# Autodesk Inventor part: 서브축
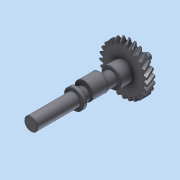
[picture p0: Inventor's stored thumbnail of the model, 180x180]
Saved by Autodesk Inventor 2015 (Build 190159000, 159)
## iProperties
Created: 2018-07
Part Number: 서브축
Material: 강철
Document SubType Name: Modeling
Designer: mduedu
Categories: <?xml version="1.0" encoding="UTF-16"?> <MemberInstance><Categories><FamilyTemplate><FamilyTemplateParameter ValueType="xs:double" Id="1" ObjectReferenceKey="da
Density: 7.85 g/cm^3
Mass: 513.764 g
Surface Area: 178.04 cm^2
Volume: 65.4477 cm^3
Appearance: 강철
Author: mduedu
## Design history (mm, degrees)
sketch "Sketch1"
  geometry: C1 r 30.864 at (0, 0)
  constraints: 1 centre point
  dimensions: "d0" = 61.72879 diameter of C1 (= da_da)
extrude "Extrusion1" new body sketch "Sketch1" distance "d1" = 10 (= da_b); taper "d2" = 0 deg
workplane "Work Plane2"
sketch "Sketch2"
  geometry: C1 r 30.864 at (0, 0) reference; C2 r 29.013 at (0, 0)
  constraints: 1 centre point, 1 coincident
  dimensions: "d3" = 58.02632 diameter of C2 (= da_dw)
feature "피치 지름" sketch "Sketch2" dims "d4" = 10, "d5" = 0
workplane "Work Plane8"
workplane "Work Plane9"
feature "스퍼 기어" dims "da_b" = 10, "da_d" = 57.73503, "da_aw" = 44.1, "da_da" = 61.72879, "da_df" = 52.73503, "da_dw" = 58.02632, angle "da_beta" = 30 deg, "da_lefttooth" = 10, "da_righttooth" = 0
sketch "스케치3"
  geometry: C1 r 12.5 at (0, 0); 1 further point
  constraints: 1 centre point, 1 coincident
  dimensions: "d49" = 25 diameter of C1
extrude "돌출2" join sketch "스케치3" distance "d50" = 16; taper "d51" = 0 deg
sketch "스케치4"
  geometry: C1 r 8.5 at (0, 0); 1 further point
  constraints: 1 centre point, 1 coincident
  dimensions: "d52" = 17 diameter of C1
extrude "돌출3" join sketch "스케치4" distance "d53" = 103; taper "d54" = 0 deg
sketch "스케치5"
  geometry: C1 r 7.5 at (0, 0); 1 further point
  constraints: 1 centre point, 1 coincident
  dimensions: "d55" = 15 diameter of C1
extrude "돌출4" join sketch "스케치5" distance "d56" = 16; taper "d57" = 0 deg
sketch "스케치6"
  geometry: C1 r 4 at (0, 0); 1 further point
  constraints: 1 centre point, 1 coincident
  dimensions: "d58" = 8 diameter of C1
extrude "돌출5" join sketch "스케치6" distance "d59" = 7; taper "d60" = 0 deg
chamfer "모따기1" distance "d61" = 0.5; stored, may be unused: second distance "d62" = 2, angle "d63" = 45 deg
fillet "모깎기1" dims "d64" = 0.5
node "작업 평면11"
sketch "스케치7"
  geometry: C1 r 8.5 at (0, 0) reference; C2 r 11.5 at (0, -3); 1 further point
  constraints: 1 centre point, 1 tangent, 1 vertical alignment
  dimensions: "d66" = 23 diameter of C2; "d67" = 3 distance of point (0, 0) C2.centre (derived)
extrude "돌출6" join sketch "스케치7" stored distance "d68" = 20; taper "d69" = 0 deg
node "작업 평면12"
sketch "스케치8"
  geometry: C1 r 12.5 at (0, 0) reference; C2 r 12.5 at (0, 0) reference; 1 further point
extrude "돌출7" join sketch "스케치8" distance "d71" = 5; taper "d72" = 0 deg
chamfer "모따기2" distance "d73" = 0.5; stored, may be unused: second distance "d74" = 2, angle "d75" = 45 deg
body "Solid1"
body "Srf1"
node "투영된 루프1"
other parameters: "d16" = 44.1 (= da_aw), "d17" = 0, "d34" = 1.25664 (computed from da_z), "d39" = 0, "d41" = 0, "d43" = 44.1 (= da_aw), "d46" = 44.1 (= da_aw), "d47" = 0, "d48" = 0, "d65" = 25, "d70" = 48
